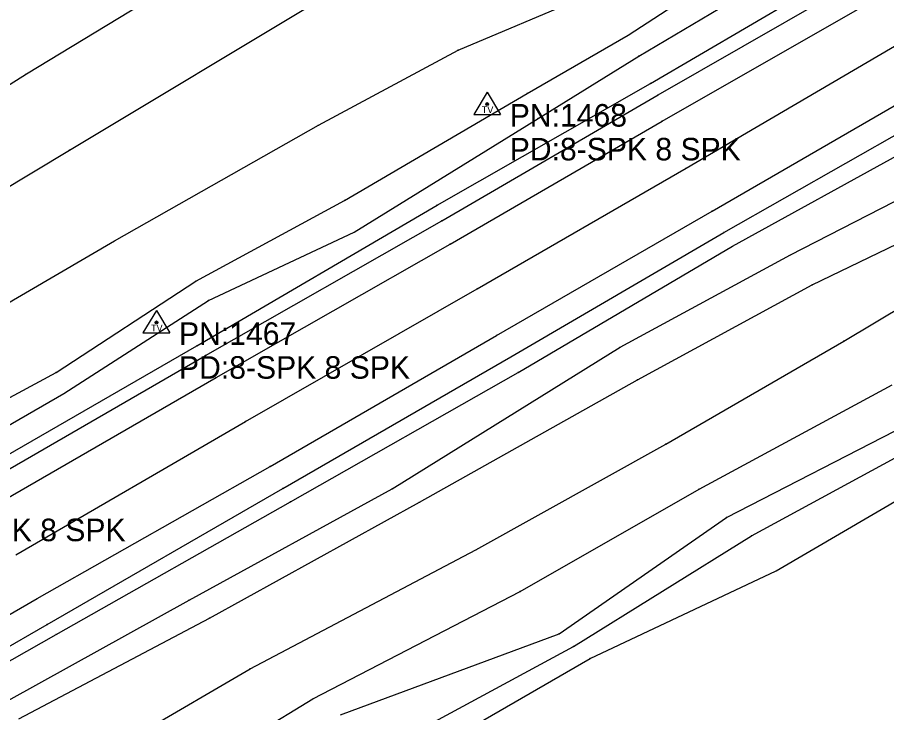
# Model space of a CAD drawing. Extents: x 1419505 to 1434054, y 1956910 to 1968644.
# Drawn here: x 1422716.6 to 1422909.5, y 1958723.8 to 1958878 of the extents above; entities that cross this region are included whole.
import ezdxf

# ---------------------------------------------------------------- set-up
doc = ezdxf.new("R2010")
doc.units = 0
for name, color, linetype in [('S_BREAKLINE', 7, 'Continuous'), ('S_DITCHLINE', 7, 'Continuous'), ('S_EDGE_PAVEMENT', 7, 'Continuous'), ('S_GRD_PT_SYM', 7, 'Continuous'), ('S_PAVEMENT_CROWN', 7, 'Continuous'), ('S_RDW_PT_SYM', 7, 'Continuous'), ('S_SECONDARY_CTL', 7, 'Continuous'), ('S_SECONDARY_CTL_ANNOT', 7, 'Continuous'), ('S_SHOULDER', 7, 'Continuous')]:
    doc.layers.add(name, color=color, linetype=linetype)

msp = doc.modelspace()

# ---------------------------------------------------------------- linework, layer by layer
at = {"layer": 'S_BREAKLINE'}
for p, q in [((1422718.6307, 1958865.5316), (1422791.0704, 1958909.4174)), ((1422852.1924, 1958874.0641), (1422884.1034, 1958895.0085)), ((1422728.1394, 1958848.5945), (1422800.7891, 1958892.1663)), ((1422857.1067, 1958863.3734), (1422904.3137, 1958890.9922)), ((1422854.5305, 1958869.4648), (1422883.0484, 1958886.3259)), ((1422814.4259, 1958870.7569), (1422845.759, 1958883.9798)), ((1422829.7299, 1958861.1353), (1422852.1924, 1958874.0641)), ((1422783.4629, 1958854.1398), (1422814.4259, 1958870.7569)), ((1422832.1611, 1958855.6399), (1422854.5305, 1958869.4648)), ((1422656.9928, 1958826.8241), (1422718.6307, 1958865.5316)), ((1422809.7456, 1958836.3937), (1422857.1067, 1958863.3734)), ((1422789.1673, 1958837.3928), (1422829.7299, 1958861.1353)), ((1422791.3844, 1958830.3733), (1422832.1611, 1958855.6399)), ((1422738.182, 1958828.4412), (1422783.4629, 1958854.1398)), ((1422875.3459, 1958827.2691), (1422923.458, 1958853.8008)), ((1422888.2257, 1958825.349), (1422946.2024, 1958855.2339)), ((1422665.1803, 1958810.731), (1422728.1394, 1958848.5945)), ((1422893.024, 1958818.6736), (1422951.6118, 1958847.1294)), ((1422900.0275, 1958806.2167), (1422962.7345, 1958843.7922)), ((1422756.1852, 1958819.5046), (1422789.1673, 1958837.3928)), ((1422756.4312, 1958805.1607), (1422809.7456, 1958836.3937)), ((1422758.9814, 1958815.2453), (1422791.3844, 1958830.3733)), ((1422712.6394, 1958813.5882), (1422738.182, 1958828.4412)), ((1422827.7188, 1958799.2273), (1422875.3459, 1958827.2691)), ((1422850.4263, 1958804.9117), (1422888.2257, 1958825.349)), ((1422725.1792, 1958799.2663), (1422756.1852, 1958819.5046)), ((1422854.2365, 1958797.6542), (1422893.024, 1958818.6736)), ((1422726.9303, 1958794.569), (1422758.9814, 1958815.2453)), ((1422706.891, 1958776.6798), (1422756.4312, 1958805.1607)), ((1422860.5259, 1958783.3713), (1422900.0275, 1958806.2167)), ((1422799.763, 1958773.4196), (1422850.4263, 1958804.9117)), ((1422690.0639, 1958780.2881), (1422725.1792, 1958799.2663)), ((1422777.2075, 1958770.5694), (1422827.7188, 1958799.2273)), ((1422805.8784, 1958770.5084), (1422854.2365, 1958797.6542)), ((1422867.9114, 1958773.4016), (1422910.7762, 1958796.5211)), ((1422694.5982, 1958776.0848), (1422726.9303, 1958794.569)), ((1422818.3742, 1958759.8908), (1422860.5259, 1958783.3713)), ((1422885.0395, 1958755.2475), (1422927.1902, 1958779.9781)), ((1422754.7091, 1958748.762), (1422799.763, 1958773.4196)), ((1422828.1878, 1958750.6902), (1422867.9114, 1958773.4016)), ((1422725.1872, 1958741.1175), (1422777.2075, 1958770.5694)), ((1422759.2164, 1958744.7848), (1422805.8784, 1958770.5084)), ((1422768.254, 1958733.5351), (1422818.3742, 1958759.8908)), ((1422843.7258, 1958735.8352), (1422885.0395, 1958755.2475)), ((1422782.2079, 1958726.8896), (1422828.1878, 1958750.6902)), ((1422714.5805, 1958726.4656), (1422754.7091, 1958748.762)), ((1422716.8996, 1958722.4643), (1422759.2164, 1958744.7848)), ((1422676.663, 1958713.6518), (1422725.1872, 1958741.1175)), ((1422806.9555, 1958714.6218), (1422843.7258, 1958735.8352)), ((1422723.6131, 1958707.5024), (1422768.254, 1958733.5351)), ((1422733.1207, 1958697.0547), (1422782.2079, 1958726.8896))]:
    msp.add_line(p, q, dxfattribs=at)
at = {"layer": 'S_DITCHLINE'}
for p, q in [((1422874.0018, 1958767.1252), (1422918.9067, 1958790.1517)), ((1422879.5211, 1958763), (1422925.1841, 1958787.7996)), ((1422836.8264, 1958741.3106), (1422874.0018, 1958767.1252)), ((1422840.0156, 1958738.5114), (1422879.5211, 1958763)), ((1422788.3242, 1958723.2914), (1422836.8264, 1958741.3106)), ((1422801.6201, 1958717.757), (1422840.0156, 1958738.5114))]:
    msp.add_line(p, q, dxfattribs=at)
at = {"layer": 'S_EDGE_PAVEMENT'}
for p, q in [((1422859.7289, 1958855.0279), (1422908.352, 1958882.8477)), ((1422870.8096, 1958835.0476), (1422918.8007, 1958862.7874)), ((1422812.6338, 1958827.7601), (1422859.7289, 1958855.0279)), ((1422822.9505, 1958807.4518), (1422870.8096, 1958835.0476)), ((1422760.7485, 1958798.1712), (1422812.6338, 1958827.7601)), ((1422772.6952, 1958778.432), (1422822.9505, 1958807.4518)), ((1422710.5292, 1958769.2204), (1422760.7485, 1958798.1712)), ((1422721.0009, 1958749.1051), (1422772.6952, 1958778.432)), ((1422673.3998, 1958721.6573), (1422721.0009, 1958749.1051))]:
    msp.add_line(p, q, dxfattribs=at)
at = {"layer": 'S_GRD_PT_SYM'}
for points in [[(1422852.1924, 1958874.0641), (1422852.1924, 1958874.1141), (1422852.1924, 1958874.0641), (1422852.1424, 1958874.0641), (1422852.1924, 1958874.0641), (1422852.1924, 1958874.0141), (1422852.1924, 1958874.0641), (1422852.2424, 1958874.0641)], [(1422814.4259, 1958870.7569), (1422814.4259, 1958870.8069), (1422814.4259, 1958870.7569), (1422814.3759, 1958870.7569), (1422814.4259, 1958870.7569), (1422814.4259, 1958870.7069), (1422814.4259, 1958870.7569), (1422814.4759, 1958870.7569)], [(1422854.5305, 1958869.4648), (1422854.5305, 1958869.5148), (1422854.5305, 1958869.4648), (1422854.4805, 1958869.4648), (1422854.5305, 1958869.4648), (1422854.5305, 1958869.4148), (1422854.5305, 1958869.4648), (1422854.5805, 1958869.4648)], [(1422718.6307, 1958865.5316), (1422718.6307, 1958865.5816), (1422718.6307, 1958865.5316), (1422718.5807, 1958865.5316), (1422718.6307, 1958865.5316), (1422718.6307, 1958865.4816), (1422718.6307, 1958865.5316), (1422718.6807, 1958865.5316)], [(1422857.1067, 1958863.3734), (1422857.1067, 1958863.4234), (1422857.1067, 1958863.3734), (1422857.0567, 1958863.3734), (1422857.1067, 1958863.3734), (1422857.1067, 1958863.3234), (1422857.1067, 1958863.3734), (1422857.1567, 1958863.3734)], [(1422829.7299, 1958861.1353), (1422829.7299, 1958861.1853), (1422829.7299, 1958861.1353), (1422829.6799, 1958861.1353), (1422829.7299, 1958861.1353), (1422829.7299, 1958861.0853), (1422829.7299, 1958861.1353), (1422829.7799, 1958861.1353)], [(1422832.1611, 1958855.6399), (1422832.1611, 1958855.6899), (1422832.1611, 1958855.6399), (1422832.1111, 1958855.6399), (1422832.1611, 1958855.6399), (1422832.1611, 1958855.5899), (1422832.1611, 1958855.6399), (1422832.2111, 1958855.6399)], [(1422783.4629, 1958854.1398), (1422783.4629, 1958854.1898), (1422783.4629, 1958854.1398), (1422783.4129, 1958854.1398), (1422783.4629, 1958854.1398), (1422783.4629, 1958854.0898), (1422783.4629, 1958854.1398), (1422783.5129, 1958854.1398)], [(1422728.1394, 1958848.5945), (1422728.1394, 1958848.6445), (1422728.1394, 1958848.5945), (1422728.0894, 1958848.5945), (1422728.1394, 1958848.5945), (1422728.1394, 1958848.5445), (1422728.1394, 1958848.5945), (1422728.1894, 1958848.5945)], [(1422789.1673, 1958837.3928), (1422789.1673, 1958837.4428), (1422789.1673, 1958837.3928), (1422789.1173, 1958837.3928), (1422789.1673, 1958837.3928), (1422789.1673, 1958837.3428), (1422789.1673, 1958837.3928), (1422789.2173, 1958837.3928)], [(1422809.7456, 1958836.3937), (1422809.7456, 1958836.4437), (1422809.7456, 1958836.3937), (1422809.6956, 1958836.3937), (1422809.7456, 1958836.3937), (1422809.7456, 1958836.3437), (1422809.7456, 1958836.3937), (1422809.7956, 1958836.3937)], [(1422791.3844, 1958830.3733), (1422791.3844, 1958830.4233), (1422791.3844, 1958830.3733), (1422791.3344, 1958830.3733), (1422791.3844, 1958830.3733), (1422791.3844, 1958830.3233), (1422791.3844, 1958830.3733), (1422791.4344, 1958830.3733)], [(1422738.182, 1958828.4412), (1422738.182, 1958828.4912), (1422738.182, 1958828.4412), (1422738.132, 1958828.4412), (1422738.182, 1958828.4412), (1422738.182, 1958828.3912), (1422738.182, 1958828.4412), (1422738.232, 1958828.4412)], [(1422875.3459, 1958827.2691), (1422875.3459, 1958827.3191), (1422875.3459, 1958827.2691), (1422875.2959, 1958827.2691), (1422875.3459, 1958827.2691), (1422875.3459, 1958827.2191), (1422875.3459, 1958827.2691), (1422875.3959, 1958827.2691)], [(1422888.2257, 1958825.349), (1422888.2257, 1958825.399), (1422888.2257, 1958825.349), (1422888.1757, 1958825.349), (1422888.2257, 1958825.349), (1422888.2257, 1958825.299), (1422888.2257, 1958825.349), (1422888.2757, 1958825.349)], [(1422756.1852, 1958819.5046), (1422756.1852, 1958819.5546), (1422756.1852, 1958819.5046), (1422756.1352, 1958819.5046), (1422756.1852, 1958819.5046), (1422756.1852, 1958819.4546), (1422756.1852, 1958819.5046), (1422756.2352, 1958819.5046)], [(1422893.024, 1958818.6736), (1422893.024, 1958818.7236), (1422893.024, 1958818.6736), (1422892.974, 1958818.6736), (1422893.024, 1958818.6736), (1422893.024, 1958818.6236), (1422893.024, 1958818.6736), (1422893.074, 1958818.6736)], [(1422758.9814, 1958815.2453), (1422758.9814, 1958815.2953), (1422758.9814, 1958815.2453), (1422758.9314, 1958815.2453), (1422758.9814, 1958815.2453), (1422758.9814, 1958815.1953), (1422758.9814, 1958815.2453), (1422759.0314, 1958815.2453)], [(1422756.4312, 1958805.1607), (1422756.4312, 1958805.2107), (1422756.4312, 1958805.1607), (1422756.3812, 1958805.1607), (1422756.4312, 1958805.1607), (1422756.4312, 1958805.1107), (1422756.4312, 1958805.1607), (1422756.4812, 1958805.1607)], [(1422900.0275, 1958806.2167), (1422900.0275, 1958806.2667), (1422900.0275, 1958806.2167), (1422899.9775, 1958806.2167), (1422900.0275, 1958806.2167), (1422900.0275, 1958806.1667), (1422900.0275, 1958806.2167), (1422900.0775, 1958806.2167)], [(1422850.4263, 1958804.9117), (1422850.4263, 1958804.9617), (1422850.4263, 1958804.9117), (1422850.3763, 1958804.9117), (1422850.4263, 1958804.9117), (1422850.4263, 1958804.8617), (1422850.4263, 1958804.9117), (1422850.4763, 1958804.9117)], [(1422725.1792, 1958799.2663), (1422725.1792, 1958799.3163), (1422725.1792, 1958799.2663), (1422725.1292, 1958799.2663), (1422725.1792, 1958799.2663), (1422725.1792, 1958799.2163), (1422725.1792, 1958799.2663), (1422725.2292, 1958799.2663)], [(1422827.7188, 1958799.2273), (1422827.7188, 1958799.2773), (1422827.7188, 1958799.2273), (1422827.6688, 1958799.2273), (1422827.7188, 1958799.2273), (1422827.7188, 1958799.1773), (1422827.7188, 1958799.2273), (1422827.7688, 1958799.2273)], [(1422854.2365, 1958797.6542), (1422854.2365, 1958797.7042), (1422854.2365, 1958797.6542), (1422854.1865, 1958797.6542), (1422854.2365, 1958797.6542), (1422854.2365, 1958797.6042), (1422854.2365, 1958797.6542), (1422854.2865, 1958797.6542)], [(1422726.9303, 1958794.569), (1422726.9303, 1958794.619), (1422726.9303, 1958794.569), (1422726.8803, 1958794.569), (1422726.9303, 1958794.569), (1422726.9303, 1958794.519), (1422726.9303, 1958794.569), (1422726.9803, 1958794.569)], [(1422860.5259, 1958783.3713), (1422860.5259, 1958783.4213), (1422860.5259, 1958783.3713), (1422860.4759, 1958783.3713), (1422860.5259, 1958783.3713), (1422860.5259, 1958783.3213), (1422860.5259, 1958783.3713), (1422860.5759, 1958783.3713)], [(1422799.763, 1958773.4196), (1422799.763, 1958773.4696), (1422799.763, 1958773.4196), (1422799.713, 1958773.4196), (1422799.763, 1958773.4196), (1422799.763, 1958773.3696), (1422799.763, 1958773.4196), (1422799.813, 1958773.4196)], [(1422867.9114, 1958773.4016), (1422867.9114, 1958773.4516), (1422867.9114, 1958773.4016), (1422867.8614, 1958773.4016), (1422867.9114, 1958773.4016), (1422867.9114, 1958773.3516), (1422867.9114, 1958773.4016), (1422867.9614, 1958773.4016)], [(1422777.2075, 1958770.5694), (1422777.2075, 1958770.6194), (1422777.2075, 1958770.5694), (1422777.1575, 1958770.5694), (1422777.2075, 1958770.5694), (1422777.2075, 1958770.5194), (1422777.2075, 1958770.5694), (1422777.2575, 1958770.5694)], [(1422805.8784, 1958770.5084), (1422805.8784, 1958770.5584), (1422805.8784, 1958770.5084), (1422805.8284, 1958770.5084), (1422805.8784, 1958770.5084), (1422805.8784, 1958770.4584), (1422805.8784, 1958770.5084), (1422805.9284, 1958770.5084)], [(1422874.0018, 1958767.1252), (1422874.0018, 1958767.1752), (1422874.0018, 1958767.1252), (1422873.9518, 1958767.1252), (1422874.0018, 1958767.1252), (1422874.0018, 1958767.0752), (1422874.0018, 1958767.1252), (1422874.0518, 1958767.1252)], [(1422879.5211, 1958763), (1422879.5211, 1958763.05), (1422879.5211, 1958763), (1422879.4711, 1958763), (1422879.5211, 1958763), (1422879.5211, 1958762.95), (1422879.5211, 1958763), (1422879.5711, 1958763)], [(1422818.3742, 1958759.8908), (1422818.3742, 1958759.9408), (1422818.3742, 1958759.8908), (1422818.3242, 1958759.8908), (1422818.3742, 1958759.8908), (1422818.3742, 1958759.8408), (1422818.3742, 1958759.8908), (1422818.4242, 1958759.8908)], [(1422885.0395, 1958755.2475), (1422885.0395, 1958755.2975), (1422885.0395, 1958755.2475), (1422884.9895, 1958755.2475), (1422885.0395, 1958755.2475), (1422885.0395, 1958755.1975), (1422885.0395, 1958755.2475), (1422885.0895, 1958755.2475)], [(1422828.1878, 1958750.6902), (1422828.1878, 1958750.7402), (1422828.1878, 1958750.6902), (1422828.1378, 1958750.6902), (1422828.1878, 1958750.6902), (1422828.1878, 1958750.6402), (1422828.1878, 1958750.6902), (1422828.2378, 1958750.6902)], [(1422754.7091, 1958748.762), (1422754.7091, 1958748.812), (1422754.7091, 1958748.762), (1422754.6591, 1958748.762), (1422754.7091, 1958748.762), (1422754.7091, 1958748.712), (1422754.7091, 1958748.762), (1422754.7591, 1958748.762)], [(1422759.2164, 1958744.7848), (1422759.2164, 1958744.8348), (1422759.2164, 1958744.7848), (1422759.1664, 1958744.7848), (1422759.2164, 1958744.7848), (1422759.2164, 1958744.7348), (1422759.2164, 1958744.7848), (1422759.2664, 1958744.7848)], [(1422725.1872, 1958741.1175), (1422725.1872, 1958741.1675), (1422725.1872, 1958741.1175), (1422725.1372, 1958741.1175), (1422725.1872, 1958741.1175), (1422725.1872, 1958741.0675), (1422725.1872, 1958741.1175), (1422725.2372, 1958741.1175)], [(1422836.8264, 1958741.3106), (1422836.8264, 1958741.3606), (1422836.8264, 1958741.3106), (1422836.7764, 1958741.3106), (1422836.8264, 1958741.3106), (1422836.8264, 1958741.2606), (1422836.8264, 1958741.3106), (1422836.8764, 1958741.3106)], [(1422840.0156, 1958738.5114), (1422840.0156, 1958738.5614), (1422840.0156, 1958738.5114), (1422839.9656, 1958738.5114), (1422840.0156, 1958738.5114), (1422840.0156, 1958738.4614), (1422840.0156, 1958738.5114), (1422840.0656, 1958738.5114)], [(1422843.7258, 1958735.8352), (1422843.7258, 1958735.8852), (1422843.7258, 1958735.8352), (1422843.6758, 1958735.8352), (1422843.7258, 1958735.8352), (1422843.7258, 1958735.7852), (1422843.7258, 1958735.8352), (1422843.7758, 1958735.8352)], [(1422768.254, 1958733.5351), (1422768.254, 1958733.5851), (1422768.254, 1958733.5351), (1422768.204, 1958733.5351), (1422768.254, 1958733.5351), (1422768.254, 1958733.4851), (1422768.254, 1958733.5351), (1422768.304, 1958733.5351)], [(1422782.2079, 1958726.8896), (1422782.2079, 1958726.9396), (1422782.2079, 1958726.8896), (1422782.1579, 1958726.8896), (1422782.2079, 1958726.8896), (1422782.2079, 1958726.8396), (1422782.2079, 1958726.8896), (1422782.2579, 1958726.8896)]]:
    msp.add_lwpolyline(points, dxfattribs=at)
at = {"layer": 'S_PAVEMENT_CROWN'}
for p, q in [((1422865.0792, 1958844.5792), (1422913.4393, 1958872.8881)), ((1422818.6562, 1958817.7845), (1422865.0792, 1958844.5792)), ((1422767.2339, 1958788.4216), (1422818.6562, 1958817.7845)), ((1422716.2366, 1958758.7937), (1422767.2339, 1958788.4216))]:
    msp.add_line(p, q, dxfattribs=at)
at = {"layer": 'S_RDW_PT_SYM'}
for points in [[(1422858.8438, 1958860.8883), (1422858.8438, 1958860.9383), (1422858.8438, 1958860.8883), (1422858.7938, 1958860.8883), (1422858.8438, 1958860.8883), (1422858.8438, 1958860.8383), (1422858.8438, 1958860.8883), (1422858.8938, 1958860.8883)], [(1422859.7289, 1958855.0279), (1422859.7289, 1958855.0779), (1422859.7289, 1958855.0279), (1422859.6789, 1958855.0279), (1422859.7289, 1958855.0279), (1422859.7289, 1958854.9779), (1422859.7289, 1958855.0279), (1422859.7789, 1958855.0279)], [(1422865.0792, 1958844.5792), (1422865.0792, 1958844.6292), (1422865.0792, 1958844.5792), (1422865.0292, 1958844.5792), (1422865.0792, 1958844.5792), (1422865.0792, 1958844.5292), (1422865.0792, 1958844.5792), (1422865.1292, 1958844.5792)], [(1422870.8096, 1958835.0476), (1422870.8096, 1958835.0976), (1422870.8096, 1958835.0476), (1422870.7596, 1958835.0476), (1422870.8096, 1958835.0476), (1422870.8096, 1958834.9976), (1422870.8096, 1958835.0476), (1422870.8596, 1958835.0476)], [(1422810.8107, 1958832.9395), (1422810.8107, 1958832.9895), (1422810.8107, 1958832.9395), (1422810.7607, 1958832.9395), (1422810.8107, 1958832.9395), (1422810.8107, 1958832.8895), (1422810.8107, 1958832.9395), (1422810.8607, 1958832.9395)], [(1422873.4137, 1958830.2983), (1422873.4137, 1958830.3483), (1422873.4137, 1958830.2983), (1422873.3637, 1958830.2983), (1422873.4137, 1958830.2983), (1422873.4137, 1958830.2483), (1422873.4137, 1958830.2983), (1422873.4637, 1958830.2983)], [(1422812.6338, 1958827.7601), (1422812.6338, 1958827.8101), (1422812.6338, 1958827.7601), (1422812.5838, 1958827.7601), (1422812.6338, 1958827.7601), (1422812.6338, 1958827.7101), (1422812.6338, 1958827.7601), (1422812.6838, 1958827.7601)], [(1422818.6562, 1958817.7845), (1422818.6562, 1958817.8345), (1422818.6562, 1958817.7845), (1422818.6062, 1958817.7845), (1422818.6562, 1958817.7845), (1422818.6562, 1958817.7345), (1422818.6562, 1958817.7845), (1422818.7062, 1958817.7845)], [(1422822.9505, 1958807.4518), (1422822.9505, 1958807.5018), (1422822.9505, 1958807.4518), (1422822.9005, 1958807.4518), (1422822.9505, 1958807.4518), (1422822.9505, 1958807.4018), (1422822.9505, 1958807.4518), (1422823.0005, 1958807.4518)], [(1422758.3413, 1958803.0565), (1422758.3413, 1958803.1065), (1422758.3413, 1958803.0565), (1422758.2913, 1958803.0565), (1422758.3413, 1958803.0565), (1422758.3413, 1958803.0065), (1422758.3413, 1958803.0565), (1422758.3913, 1958803.0565)], [(1422826.1407, 1958802.7145), (1422826.1407, 1958802.7645), (1422826.1407, 1958802.7145), (1422826.0907, 1958802.7145), (1422826.1407, 1958802.7145), (1422826.1407, 1958802.6645), (1422826.1407, 1958802.7145), (1422826.1907, 1958802.7145)], [(1422760.7485, 1958798.1712), (1422760.7485, 1958798.2212), (1422760.7485, 1958798.1712), (1422760.6985, 1958798.1712), (1422760.7485, 1958798.1712), (1422760.7485, 1958798.1212), (1422760.7485, 1958798.1712), (1422760.7985, 1958798.1712)], [(1422767.2339, 1958788.4216), (1422767.2339, 1958788.4716), (1422767.2339, 1958788.4216), (1422767.1839, 1958788.4216), (1422767.2339, 1958788.4216), (1422767.2339, 1958788.3716), (1422767.2339, 1958788.4216), (1422767.2839, 1958788.4216)], [(1422772.6952, 1958778.432), (1422772.6952, 1958778.482), (1422772.6952, 1958778.432), (1422772.6452, 1958778.432), (1422772.6952, 1958778.432), (1422772.6952, 1958778.382), (1422772.6952, 1958778.432), (1422772.7452, 1958778.432)], [(1422775.4914, 1958773.5586), (1422775.4914, 1958773.6086), (1422775.4914, 1958773.5586), (1422775.4414, 1958773.5586), (1422775.4914, 1958773.5586), (1422775.4914, 1958773.5086), (1422775.4914, 1958773.5586), (1422775.5414, 1958773.5586)], [(1422721.0009, 1958749.1051), (1422721.0009, 1958749.1551), (1422721.0009, 1958749.1051), (1422720.9509, 1958749.1051), (1422721.0009, 1958749.1051), (1422721.0009, 1958749.0551), (1422721.0009, 1958749.1051), (1422721.0509, 1958749.1051)], [(1422723.193, 1958743.3637), (1422723.193, 1958743.4137), (1422723.193, 1958743.3637), (1422723.143, 1958743.3637), (1422723.193, 1958743.3637), (1422723.193, 1958743.3137), (1422723.193, 1958743.3637), (1422723.243, 1958743.3637)]]:
    msp.add_lwpolyline(points, dxfattribs=at)
at = {"layer": 'S_SECONDARY_CTL'}
for p, q in [((1422820.8864, 1958861.4182), (1422817.8764, 1958856.4643)), ((1422820.8864, 1958861.4182), (1422823.8337, 1958856.4643)), ((1422817.8764, 1958856.4643), (1422823.8337, 1958856.4643)), ((1422747.4676, 1958812.9931), (1422744.4576, 1958808.0392)), ((1422747.4676, 1958812.9931), (1422750.4149, 1958808.0392)), ((1422744.4576, 1958808.0392), (1422750.4149, 1958808.0392))]:
    msp.add_line(p, q, dxfattribs=at)
for centre, radius in [((1422820.8864, 1958858.8081), 0.3111), ((1422820.8864, 1958858.8081), 0.1827), ((1422820.8864, 1958858.8081), 0.1033), ((1422747.4676, 1958810.383), 0.3111), ((1422747.4676, 1958810.383), 0.1827), ((1422747.4676, 1958810.383), 0.1033)]:
    msp.add_circle(centre, radius, dxfattribs=at)
at = {"layer": 'S_SHOULDER'}
for p, q in [((1422858.8438, 1958860.8883), (1422905.4188, 1958887.527)), ((1422810.8107, 1958832.9395), (1422858.8438, 1958860.8883)), ((1422873.4137, 1958830.2983), (1422921.5629, 1958857.7121)), ((1422758.3413, 1958803.0565), (1422810.8107, 1958832.9395)), ((1422826.1407, 1958802.7145), (1422873.4137, 1958830.2983)), ((1422707.8591, 1958773.8337), (1422758.3413, 1958803.0565)), ((1422775.4914, 1958773.5586), (1422826.1407, 1958802.7145)), ((1422723.193, 1958743.3637), (1422775.4914, 1958773.5586)), ((1422675.803, 1958716.0429), (1422723.193, 1958743.3637))]:
    msp.add_line(p, q, dxfattribs=at)

# ---------------------------------------------------------------- texts
at = {"layer": 'S_SECONDARY_CTL'}
for p in [(1422819.6817, 1958856.7968), (1422746.2629, 1958808.3717)]:
    msp.add_text('TV', height=1.5, rotation=360, dxfattribs=at).set_placement(p)
at = {"layer": 'S_SECONDARY_CTL_ANNOT'}
for s, p in [('PN:1468', (1422825.8864, 1958853.8081)), ('PD:8-SPK 8 SPK', (1422825.8864, 1958846.3081)), ('PN:1467', (1422752.4676, 1958805.383)), ('PD:8-SPK 8 SPK', (1422752.4676, 1958797.883)), ('PD:8-SPK 8 SPK', (1422689.3215, 1958761.8387))]:
    msp.add_text(s, height=5, dxfattribs=at).set_placement(p)

doc.saveas('drawing.dxf')
